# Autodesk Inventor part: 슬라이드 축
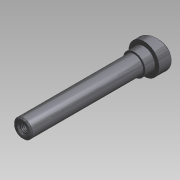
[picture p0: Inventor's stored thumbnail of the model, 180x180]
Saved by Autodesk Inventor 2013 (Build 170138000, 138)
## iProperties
Company: 한국ATC센터
Created: 2014-07
Part Number: 슬라이드 축
Document SubType Name: 모델링
Designer: KYOUNG IL JANG
Mass: 12.296 g
Surface Area: 67.5858 cm^2
Volume: 21.572 cm^3
Density: 0.57 g/cm^3
Material: 강철, 연강
변환 표준: STEP AP214IS
파일 이름: C:\Users\SeoGD\Desktop\?쒗뿕\異?stp
전처리기: Build: 253, Release: 2010 SP1 - Date: Wed 07/29/2009
전송 단위: 밀리미터
불확실성: 0.01
Author: KYOUNG IL JANG
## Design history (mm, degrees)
sketch "스케치1"
  geometry: L1 (0, 100)-(7.5, 100); L2 (7.5, 100)-(7.5, 0); L3 (7.5, 0)-(12.5, 0); L4 (12.5, 0)-(12.5, -17); L5 (12.5, -17)-(0, -17); L6 (0, -17)-(0, 100); 1 further point
  constraints: 12 end point, 2 parallel, 2 point on line, 1 perpendicular, 1 vertical
  dimensions: "d0" = 100 distance from line of L1 point (0, 0); "d1" = 15 diameter of L2 L6; "d2" = 25 diameter of L4 L6; "d3" = 17 distance of L3.end L4.end
revolve "회전1" sketch "스케치1" stored, may be unused: angle "d4" = 90 deg
sketch "스케치2"
  geometry: L1 (12.5, 0)-(12.5, -17) reference; L2 (-12.5, -17)-(12.5, -17) reference; L3 (-12.5, 0)-(-12.5, -17) reference; L4 (12.5, -5)-(-12.5, -11.699); L5 (-12.5, 0)-(12.5, 0) reference; 1 further point
  constraints: 2 end point, 2 point on line
  dimensions: "d5" = 75 deg angle of L1 L4; "d6" = 5 distance from line of L4.start L5
extrude "돌출1" cut sketch "스케치2" stored distance "d7" = 10; taper "d8" = 0 deg
chamfer "모따기1" distance "d9" = 1; stored, may be unused: second distance "d10" = 2, angle "d11" = 45 deg
fillet "모깎기1" dims "d12" = 0.5
hole "구멍1" diameter "d15" = 6.647; stored, may be unused: countersink angle "d19" = 90 deg, drill point angle "d21" = 118 deg; dims "d13" = 10, "d14" = 10, "d16" = 17, "d17" = 4, "d18" = 2, "d20" = 20
chamfer "모따기2" distance "d22" = 1; stored, may be unused: second distance "d23" = 2, angle "d24" = 45 deg
sketch "스케치3"
  geometry: C1 r 9 at (0, 0); 1 further point
  constraints: 1 centre point, 1 coincident
  dimensions: "d25" = 18 diameter of C1
extrude "돌출2" join sketch "스케치3" distance "d26" = 8; taper "d27" = 0 deg
node "솔리드1"
node "솔리드 본체"
node "곡면 본체"
node "솔리드2"
